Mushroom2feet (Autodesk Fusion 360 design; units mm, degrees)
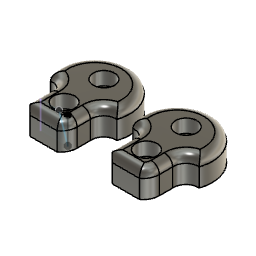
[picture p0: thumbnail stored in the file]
sketch "Sketch1" plane through (0, 0, 0) normal (0, 0, 1) x axis (1, 0, 0)
  line L1 (-7.5182, -15) -> (-17.7456, -15)
  line L2 (-20, -5) -> (-20, -10.9164)
  line L3 (-5, -5) -> (-5, -10)
  arc A1 centre (-12.5, 4.1667) radius 13.1762 clockwise from (-25, 0) to (0, 0)
  arc A2 centre (-11.223, -10) radius 6.223 clockwise from (-5, -10) to (-7.5182, -15)
  arc A3 centre (-24.4348, -4.4348) radius 4.4707 clockwise from (-25, 0) to (-20, -5)
  arc A4 centre (-0.3795, -4.6205) radius 4.6361 clockwise from (-5, -5) to (0, 0)
  arc A5 centre (-14.0927, -10.3193) radius 5.9374 clockwise from (-17.7456, -15) to (-20, -10.9164)
  point P1 (0, 0)
  point P3 (0, 0)
  point P13 (0, 0)
  coincident P1 P3
  horizontal L1
  tangent L3 A2
  coincident P1 P13
extrude "Extrude1" new body sketch "Sketch1" profile of A1 L1 L2 L3 A2 A3 A4 along normal blind 10
sketch "Sketch2" plane through (0, -15, 0) normal (0, -1, 0) x axis (1, 0, 0)
  line L1 (-7.5182, 0) -> (-17.7456, 0)
  line L2 (-7.5182, 10) -> (-7.5182, 0)
  line L3 (-17.7456, 10) -> (-7.5182, 10)
  line L4 (-7.5182, 0) -> (-10.8323, 10)
  line L5 (-10.8323, 10) -> (-7.5182, 10)
  line L6 (-7.5182, 0) -> (-7.5182, 10)
  line L7 (-7.5182, 10) -> (-10.8323, 10)
  line L8 (-17.7456, 0) -> (-17.7456, 10)
  point P6 (-10.8323, 10)
  point P3 (-7.5182, 0)
  point P7 (-7.5182, 0)
  point P4 (-7.5182, 10)
  point P8 (-7.5182, 10)
  coincident L3 P6
  coincident P3 P7
  coincident P4 P8
  perpendicular L2 L5
fillet "Fillet1" radius 3.1
hole "Hole1" HoleDepth 15 HoleDiameter 6 TipAngle 180 CBDepth 5 CBDiameter 8
rectangular_pattern "R-Pattern1" uSpaceDistance -15 vSpaceDistance 0
rectangular_pattern "R-Pattern2" uSpaceDistance 31 vSpaceDistance 0
move "Move2"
